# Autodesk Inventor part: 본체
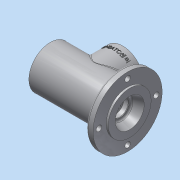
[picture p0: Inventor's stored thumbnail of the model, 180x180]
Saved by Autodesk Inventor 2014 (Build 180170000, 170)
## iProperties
Created: 2016-08
Part Number: 본체
Material: 알루미늄 6061
Document SubType Name: Modeling
Designer: 402-003
Density: 2.71 g/cm^3
Appearance: 알루미늄 - 평지
Mass: 730.337 g
Surface Area: 616.977 cm^2
Volume: 269.497 cm^3
Author: 402-003
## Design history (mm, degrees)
sketch "스케치5"
  geometry: C1 r 50 at (0, 0); 1 further point
  constraints: 1 centre point, 1 coincident
  dimensions: "d6" = 100 diameter of C1
extrude "돌출3" new body sketch "스케치5" distance "d7" = 10; taper "d8" = 0 deg
sketch "스케치6"
  geometry: C1 r 50 at (0, 0) reference; C2 r 31 at (0, 0)
  constraints: 1 centre point, 1 coincident
  dimensions: "d9" = 62 diameter of C2
extrude "돌출4" join sketch "스케치6" distance "d10" = 3; taper "d11" = 0 deg
sketch "스케치7"
  geometry: C1 r 50 at (0, 0) reference; C2 r 31 at (0, 0)
  constraints: 1 centre point, 1 coincident
  dimensions: "d12" = 62 diameter of C2
extrude "돌출5" join sketch "스케치7" distance "d13" = 102; taper "d14" = 0 deg
sketch "스케치8"
  geometry: L1 (3, 0)-(-103, 0); L2 (-112, 31)-(-112, -31) reference; L3 (3, -31)-(3, 31) reference; L4 (-103, 0)-(-103, 24); L5 (-103, 24)-(-100, 24); L6 (-100, 24)-(-100, 20); L7 (-100, 20)-(-91, 20); L8 (-91, 20)-(-91, 17.5); L9 (-91, 17.5)-(-87.75, 17.5); L10 (-87.75, 17.5)-(-87.75, 18.5); L11 (-87.75, 18.5)-(-86, 18.5); L12 (-86, 18.5)-(-86, 17.5); L13 (-11, 12.904)-(-11, 13.886); L14 (-9.009, 16.711)-(3, 21); L15 (-11.7, 12.5)-(-11, 12.904); L16 (-11.7, 12.5)-(-18, 12.5); L17 (-18.3, 12.2)-(-18.3, 10); L18 (-18.3, 10)-(-21, 10); L19 (-26, 17.2)-(-26, 16.5); L20 (-26, 16.5)-(-24, 16.5); L21 (-21, 13.5)-(-21, 10); L22 (3, 21)-(3, 0); L23 (-75, 26)-(-37, 26); L24 (-37, 26)-(-37, 17.5); L25 (-75, 17.5)-(-75, 26); L26 (-86, 17.5)-(-75, 17.5); L27 (-37, 17.5)-(-26.3, 17.5); A1 r 0.3 centre (-18, 12.2) between (-18, 12.5) and (-18.3, 12.2); A2 r 3 centre (-24, 13.5) between (-21, 13.5) and (-24, 16.5); A3 r 3 centre (-8, 13.886) between (-9.009, 16.711) and (-11, 13.886); A4 r 0.3 centre (-26.3, 17.2) between (-26, 17.2) and (-26.3, 17.5); 5 further points
  constraints: 50 end point, 15 parallel, 8 point on circle, 8 tangent, 7 point on line, 6 perpendicular, 4 centre point, 2 horizontal, 2 midpoint, 2 vertical, 1 collinear
  dimensions: "d15" = 48 diameter of L5 L1; "d16" = 3 distance of L4.end L5.end; "d17" = 40 diameter of L7 L1; "d18" = 35 diameter of L9 L1; "d19" = 37 diameter of L11 L1; "d20" = 1.75 distance of L10.end L11.end; "d21" = 15.25 distance from line of L4 L10.end; "d23" = 42 diameter of L14.end L1; "d24" = 32 diameter of point (-11, 16) L1; "d25" = 0.7 horizontal distance of L13.start L15.start; "d26" = 7.3 horizontal distance of point (-18.3, 12.5) L13.start; "d27" = 25 diameter of L16 L1; "d28" = 2.7 distance of L18.end L17.end; "d29" = 20 diameter of L18 L1; "d30" = 30 deg angle of L16 L15; "d31" = 0.3 radius of A1; "d32" = 14 horizontal distance of point (-11, 16) L14.end; "d33" = 33 diameter of L20 L1; "d36" = 3 radius of A2; "d37" = 9 distance of L6.end L7.end; "d38" = 9 distance between parallel lines of L2 L4; "d60" = 52 diameter of L23 L1; "d61" = 60 distance between parallel lines of L19 L12; "d62" = 35 diameter of L27 L1; "d63" = 38 distance of L23.start L23.end; "d64" = 56 distance from line of L2 point (-56, 26); "d96" = 3 radius of A3; "d97" = 0.3 radius of A4
revolve "회전1" sketch "스케치8" stored, may be unused: angle "d45" = 90 deg
hole "구멍1" diameter "d48" = 40.376; stored, may be unused: countersink angle "d52" = 90 deg, drill point angle "d54" = 118 deg; dims "d46" = 10, "d47" = 10, "d49" = 9, "d50" = 4, "d51" = 2, "d53" = 9
node "작업 평면1"
sketch "스케치9"
  geometry: L1 (112, -31)-(112, 31) reference; C1 r 30 at (56, 0); 1 further point
  constraints: 1 centre point, 1 horizontal alignment
  dimensions: "d56" = 60 diameter of C1; "d57" = 56 distance from line of L1 C1.centre
extrude "돌출6" join sketch "스케치9" stored distance "d58" = 102; taper "d59" = 0 deg
hole "구멍2" diameter "d67" = 38; stored, may be unused: countersink angle "d71" = 90 deg, drill point angle "d73" = 118 deg; dims "d65" = 10, "d66" = 10, "d68" = 9, "d69" = 4, "d70" = 2, "d72" = 9
sketch "스케치10" dims "d74" = 48
  geometry: C1 r 19 at (0, 0) reference; C2 r 30 at (0, 0) reference; 3 further points
  constraints: 2 vertical alignment, 1 coincident, 2 other
hole "구멍3" sketch "스케치10" at (0, 24) diameter "d75" = 3.242; stored, may be unused: countersink angle "d79" = 90 deg, drill point angle "d81" = 118 deg; dims "d76" = 8, "d77" = 4, "d78" = 2, "d80" = 10
sketch "스케치11" dims "d85" = 83
  geometry: C1 r 31 at (0, 0) reference; 2 further points
  constraints: 2 vertical alignment, 1 coincident, 2 other
hole "구멍4" sketch "스케치11" at (0, 41.5) diameter "d86" = 8; stored, may be unused: countersink angle "d90" = 90 deg, drill point angle "d92" = 118 deg; dims "d87" = 8, "d88" = 4, "d89" = 2, "d91" = 10
fillet "모깎기1" dims "d98" = 3
fillet "모깎기2" dims "d99" = 3
node "작업 평면2"
sketch "스케치12"
  geometry: L1 (-56, -18)-(-56, -80) reference; L2 (-30, 0)-(30, 0) reference; 2 further points
  constraints: 1 other
  dimensions: "d100" = 56 distance from line of L1 point (0, -10); "d101" = 10 distance from line of L2 point (0, -10)
feature "엠보싱1" sketch "스케치12" dims "d102" = 0.5, "d103" = 0
chamfer "모따기1" distance "d104" = 1; stored, may be unused: second distance "d105" = 2, angle "d106" = 45 deg
node "솔리드3"
pattern_circular "원형 패턴1" dims angle "d83" = 360 deg
pattern_circular "원형 패턴2" dims angle "d94" = 360 deg
other parameters: "d34" = 35, "d55" = 49
